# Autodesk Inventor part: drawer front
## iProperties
Created: 2005-05
Part Number: drawer front
Material: cherry
Document SubType Name: Modeling
Designer: a.campbell
Manufacturer: Standard
Standards Organization: Custom
length: 160
thickness: 19
width: 350
Author: a.campbell
Comments: machine to detail
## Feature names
1. Extrusion1
